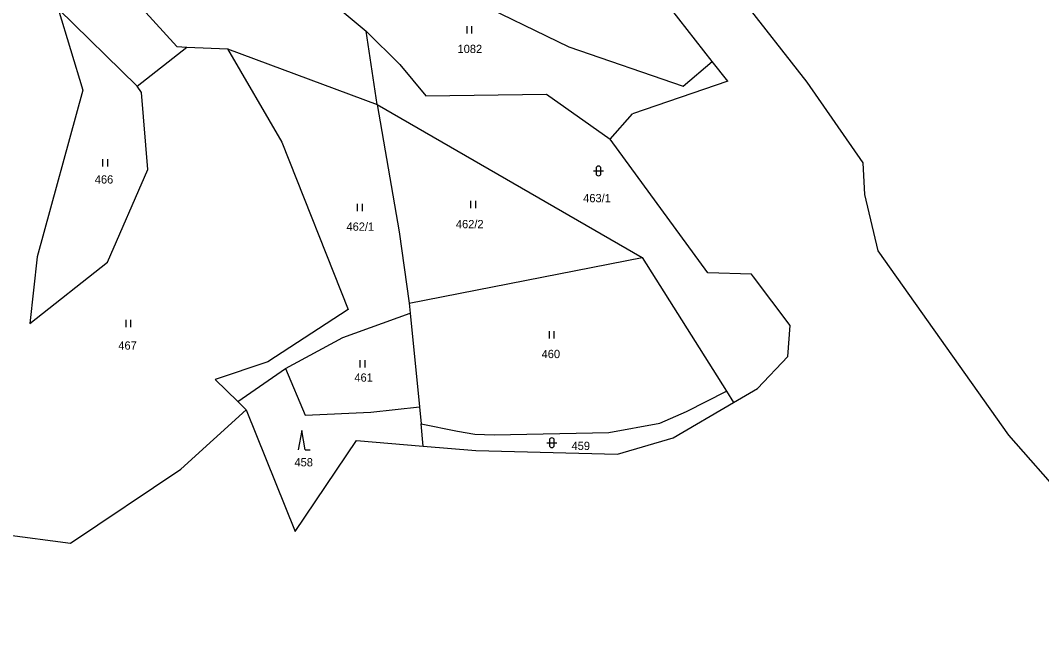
# Model space of a CAD drawing. Extents: x -744132 to -742433, y -984679 to -982287.
# Drawn here: x -742886.3 to -742676.3, y -983657.8 to -983532.9 of the extents above; entities that cross this region are included whole.
import ezdxf

# ---------------------------------------------------------------- set-up
doc = ezdxf.new("R2010")
doc.units = 0
doc.header["$LTSCALE"] = 0.68
doc.layers.add('1', color=7, linetype='Continuous', lineweight=25)
doc.layers.add('3', color=7, linetype='Continuous', lineweight=25)
doc.layers.add('2', color=7, linetype='Continuous')

msp = doc.modelspace()

# ---------------------------------------------------------------- linework, layer by layer
at = {"layer": '1'}
for p, q in [((-742879.72, -983509.89), (-742854.13, -983538.21)), ((-742744, -983541.27), (-742761.39, -983519.03)), ((-742745.89, -983518.26), (-742724.55, -983545.57)), ((-742807.71, -983521.62), (-742773.47, -983538.27)), ((-742878.49, -983530.5), (-742873.4, -983547.18)), ((-742878.49, -983530.5), (-742862.24, -983546.4)), ((-742821.72, -983529.55), (-742815.15, -983535.07)), ((-742812.91, -983550.14), (-742815.15, -983535.07)), ((-742815.15, -983535.07), (-742808.23, -983541.89)), ((-742862.24, -983546.4), (-742852.06, -983538.35)), ((-742854.13, -983538.21), (-742852.06, -983538.35)), ((-742852.06, -983538.35), (-742843.69, -983538.71)), ((-742843.69, -983538.71), (-742832.54, -983557.92)), ((-742843.69, -983538.71), (-742812.91, -983550.14)), ((-742773.47, -983538.27), (-742749.97, -983546.39)), ((-742808.23, -983541.89), (-742802.91, -983548.37)), ((-742749.97, -983546.39), (-742744, -983541.27)), ((-742740.79, -983545.38), (-742744, -983541.27)), ((-742873.4, -983547.18), (-742882.82, -983581.5)), ((-742861.36, -983547.65), (-742862.24, -983546.4)), ((-742740.79, -983545.38), (-742760.42, -983552.07)), ((-742724.55, -983545.57), (-742713.04, -983562.14)), ((-742860.03, -983563.5), (-742861.36, -983547.65)), ((-742802.91, -983548.37), (-742778.11, -983548)), ((-742778.11, -983548), (-742764.99, -983557.28)), ((-742812.91, -983550.14), (-742808.38, -983576.35)), ((-742812.91, -983550.14), (-742758.42, -983581.63)), ((-742764.99, -983557.28), (-742760.42, -983552.07)), ((-742744.91, -983584.79), (-742764.99, -983557.28)), ((-742832.54, -983557.92), (-742818.89, -983592.35)), ((-742868.39, -983582.56), (-742860.03, -983563.5)), ((-742713.04, -983562.14), (-742712.7, -983568.69)), ((-742712.7, -983568.69), (-742709.94, -983580.29)), ((-742808.38, -983576.35), (-742806.32, -983591)), ((-742709.94, -983580.29), (-742683.1, -983618.19)), ((-742882.82, -983581.5), (-742884.32, -983595.21)), ((-742884.32, -983595.21), (-742868.39, -983582.56)), ((-742806.32, -983591), (-742758.42, -983581.63)), ((-742758.42, -983581.63), (-742741.08, -983609.11)), ((-742735.95, -983585.05), (-742744.91, -983584.79)), ((-742735.51, -983585.63), (-742735.95, -983585.05)), ((-742728.01, -983595.64), (-742735.51, -983585.63)), ((-742806.32, -983591), (-742806.12, -983593.07)), ((-742818.89, -983592.35), (-742835.42, -983603.08)), ((-742819.95, -983598.1), (-742806.12, -983593.07)), ((-742806.12, -983593.07), (-742804.23, -983612.35)), ((-742728.5, -983602.03), (-742728.01, -983595.64)), ((-742831.77, -983604.48), (-742819.95, -983598.1)), ((-742835.42, -983603.08), (-742846.23, -983606.73)), ((-742734.68, -983608.57), (-742728.5, -983602.03)), ((-742841.58, -983611.27), (-742831.77, -983604.48)), ((-742831.77, -983604.48), (-742827.72, -983614.08)), ((-742846.23, -983606.73), (-742841.58, -983611.27)), ((-742749.3, -983613.28), (-742741.08, -983609.11)), ((-742741.08, -983609.11), (-742739.61, -983611.44)), ((-742739.61, -983611.44), (-742734.68, -983608.57)), ((-742841.58, -983611.27), (-742839.83, -983612.98)), ((-742814.24, -983613.43), (-742804.23, -983612.35)), ((-742804.23, -983612.35), (-742803.89, -983615.83)), ((-742752.08, -983618.7), (-742739.61, -983611.44)), ((-742853.29, -983625.17), (-742839.83, -983612.98)), ((-742839.83, -983612.98), (-742829.74, -983638.01)), ((-742827.72, -983614.08), (-742814.24, -983613.43)), ((-742754.81, -983615.7), (-742749.3, -983613.28)), ((-742803.44, -983620.45), (-742803.89, -983615.83)), ((-742803.89, -983615.83), (-742796.38, -983617.37)), ((-742765.25, -983617.63), (-742754.81, -983615.7)), ((-742796.38, -983617.37), (-742792.83, -983617.99)), ((-742792.83, -983617.99), (-742788.84, -983618.11)), ((-742788.84, -983618.11), (-742765.25, -983617.63)), ((-742763.49, -983622.08), (-742752.08, -983618.7)), ((-742683.1, -983618.19), (-742664.68, -983639.13)), ((-742829.74, -983638.01), (-742817.15, -983619.29)), ((-742817.15, -983619.29), (-742803.44, -983620.45)), ((-742803.44, -983620.45), (-742792.62, -983621.36)), ((-742792.62, -983621.36), (-742763.49, -983622.08)), ((-742875.93, -983640.4), (-742853.29, -983625.17))]:
    msp.add_line(p, q, dxfattribs=at)
msp.add_lwpolyline([(-742910.14, -983657.77), (-742903.04, -983636.86), (-742875.93, -983640.4)], dxfattribs=at)
at = {"layer": '3'}
for p, q in [((-742794.431, -983535.51), (-742794.431, -983534.01)), ((-742793.43, -983535.51), (-742793.43, -983534.01)), ((-742869.311, -983562.88), (-742869.311, -983561.38)), ((-742868.31, -983562.88), (-742868.31, -983561.38)), ((-742768.401, -983563.831), (-742766.399, -983563.831)), ((-742767.901, -983563.331), (-742767.901, -983564.332)), ((-742766.899, -983564.332), (-742766.899, -983563.331)), ((-742793.651, -983571.45), (-742793.651, -983569.95)), ((-742792.65, -983571.45), (-742792.65, -983569.95)), ((-742816.941, -983572.12), (-742816.941, -983570.62)), ((-742815.94, -983572.12), (-742815.94, -983570.62)), ((-742864.541, -983595.96), (-742864.541, -983594.46)), ((-742863.54, -983595.96), (-742863.54, -983594.46)), ((-742777.501, -983598.3), (-742777.501, -983596.8)), ((-742776.5, -983598.3), (-742776.5, -983596.8)), ((-742816.411, -983604.23), (-742816.411, -983602.73)), ((-742815.41, -983604.23), (-742815.41, -983602.73)), ((-742777.991, -983619.731), (-742775.989, -983619.731)), ((-742777.491, -983619.231), (-742777.491, -983620.232)), ((-742776.489, -983620.232), (-742776.489, -983619.231)), ((-742827.68, -983621.22), (-742826.684, -983621.22))]:
    msp.add_line(p, q, dxfattribs=at)
msp.add_lwpolyline([(-742827.68, -983621.22), (-742828.43, -983617.22), (-742829.18, -983621.22)], dxfattribs=at)
for centre, start, end in [((-742767.4, -983563.3309), 0, 180), ((-742767.4, -983564.3309), 180, 359.98789), ((-742776.99, -983619.2309), 0, 180), ((-742776.99, -983620.2309), 180, 359.98789)]:
    msp.add_arc(centre, 0.5, start, end, dxfattribs=at)

# ---------------------------------------------------------------- texts
at = {"layer": '2'}
for s, p in [('1082', (-742796.38, -983539.565)), ('466', (-742870.97, -983566.415)), ('463/1', (-742770.55, -983570.265)), ('462/1', (-742819.22, -983576.125)), ('462/2', (-742796.72, -983575.605)), ('467', (-742866.13, -983600.585)), ('460', (-742779.09, -983602.325)), ('461', (-742817.59, -983607.175)), ('459', (-742772.94, -983621.235)), ('458', (-742829.91, -983624.605))]:
    msp.add_text(s, height=1.7, dxfattribs=at).set_placement(p)

doc.saveas('drawing.dxf')
